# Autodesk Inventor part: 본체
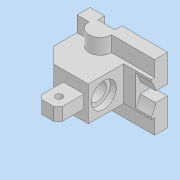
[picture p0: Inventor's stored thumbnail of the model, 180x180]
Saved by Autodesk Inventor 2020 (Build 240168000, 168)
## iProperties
Created: 2022-08
Part Number: 본체
Material: 일반
Document SubType Name: Modeling
Designer: MIRAE
Density: 1 g/cm^3
Appearance: 기본값
Author: MIRAE
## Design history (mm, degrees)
sketch "스케치1"
  geometry: L1 (-45, 38)-(45, 38); L2 (45, 38)-(45, -38); L3 (45, -38)-(-45, -38); L4 (-45, -38)-(-45, 38); L5 (-45, 38)-(45, -38); L6 (45, 38)-(-45, -38); 1 further point
  constraints: 12 end point, 2 midpoint, 2 parallel, 1 horizontal, 1 perpendicular
  dimensions: "d0" = 90 distance of L2.end L3.end; "d1" = 76 distance of L1.end L2.end
extrude "돌출1" new body sketch "스케치1" distance "d2" = 15; taper "d3" = 0 deg
sketch "스케치2"
  geometry: L1 (-45, 38)-(-45, -38) reference; L2 (-45, 20)-(13, 20); L3 (13, 20)-(13, -20); L4 (13, -20)-(-45, -20); L5 (-45, -20)-(-45, 20); L6 (-45, 0)-(64.688, 0); L7 (45, -38)-(45, 38) reference; 2 further points
  constraints: 10 end point, 2 horizontal, 2 midpoint, 2 parallel, 1 perpendicular, 1 point on line
  dimensions: "d4" = 40 distance between parallel lines of L4 L2; "d5" = 32 distance between parallel lines of L7 L3
extrude "돌출2" join sketch "스케치2" distance "d6" = 45; taper "d7" = 0 deg
chamfer "모따기1" distance "d8" = 18; stored, may be unused: second distance "d9" = 2, angle "d10" = 45 deg
sketch "스케치3"
  geometry: L1 (17, 8)-(37, 8); L2 (37, 8)-(37, -8.413); L3 (37, -8.413)-(17, -8.413); L4 (17, -8.413)-(17, 8); L5 (0, 0)-(90, 0) reference; L6 (27, 8)-(27, -18.381); L7 (0, 0)-(0, 15) reference; 1 further point
  constraints: 10 end point, 2 parallel, 1 horizontal, 1 midpoint, 1 perpendicular, 1 vertical
  dimensions: "d11" = 8 distance between parallel lines of L5 L1; "d12" = 27 distance between parallel lines of L7 L6; "d13" = 20 distance between parallel lines of L4 L2
extrude "돌출3" cut sketch "스케치3" extent not by distance; stored distance "d14" = 0; taper "d15" = 0 deg
sketch "스케치4"
  geometry: L1 (37, -7)-(17, -7) reference; L2 (27, -7)-(27, 0); L3 (0, 0)-(90, 0) reference; A1 r 13 centre (27, 0) between (40, 0) and (14, 0); 1 further point
  constraints: 3 point on line, 2 end point, 2 point on circle, 1 centre point, 1 coincident, 1 midpoint, 1 vertical
  dimensions: "d16" = 26 diameter of A1
extrude "돌출4" join sketch "스케치4" stored distance "d17" = 45; taper "d18" = 0 deg
sketch "스케치5"
  geometry: L1 (13, 20)-(13, -20) reference; L2 (45, -38)-(45, 38) reference; L3 (13, 20)-(45, 20); L4 (45, 20)-(45, -20); L5 (45, -20)-(13, -20); L6 (13, -20)-(13, 20); L7 (-27, -20)-(13, -20) reference; 2 further points
  constraints: 8 end point, 2 parallel, 2 point on line, 1 horizontal, 1 perpendicular
extrude "돌출5" join sketch "스케치5" distance "d19" = 4; taper "d20" = 0 deg
sketch "스케치6"
  geometry: L1 (16, 90)-(-8, 90); L2 (-8, 90)-(-8, 52.862); L3 (-8, 52.862)-(16, 52.862); L4 (16, 52.862)-(16, 90); L5 (-13, 60)-(27, 60) reference; L6 (-13, 19)-(-13, 60) reference; 1 further point
  constraints: 8 end point, 2 parallel, 1 horizontal, 1 perpendicular
  dimensions: "d21" = 5 distance between parallel lines of L6 L2; "d22" = 24 distance between parallel lines of L4 L2; "d23" = 30 distance between parallel lines of L5 L1
extrude "돌출6" join sketch "스케치6" stored distance "d24" = 15; taper "d25" = 0 deg
chamfer "모따기2" distance "d26" = 5; stored, may be unused: second distance "d27" = 2, angle "d28" = 45 deg
sketch "스케치7"
  geometry: L1 (60, -18)-(60, 58) reference; 4 further points
  constraints: 2 midpoint, 1 horizontal alignment
  dimensions: "d30" = 42 distance from line of L1 point (18, 20)
hole "구멍1" sketch "스케치7" at (18, 20) diameter "d31" = 20; stored, may be unused: countersink angle "d35" = 90 deg, drill point angle "d37" = 118 deg; dims "d32" = 3, "d33" = 29, "d34" = 7, "d36" = 8
sketch "스케치8"
  geometry: C1 r 10 at (-42, 38) reference; C2 r 29 at (-42, 38); 1 further point
  constraints: 1 centre point, 1 coincident
  dimensions: "d38" = 58 diameter of C2
extrude "돌출7" cut sketch "스케치8" distance "d39" = 18; taper "d40" = 0 deg
sketch "스케치9"
  geometry: L1 (8.301, 32)-(-17.655, 32); L2 (-17.655, 32)-(-17.655, 44); L3 (-17.655, 44)-(8.301, 44); L4 (8.301, 44)-(8.301, 32); L5 (0, 0)-(0, 76) reference; 3 further points
  constraints: 8 end point, 2 midpoint, 2 parallel, 1 horizontal, 1 horizontal alignment, 1 perpendicular
  dimensions: "d41" = 12 distance between parallel lines of L1 L3
extrude "돌출8" cut sketch "스케치9" distance "d42" = 18; taper "d43" = 0 deg
sketch "스케치10"
  geometry: L1 (-6, 56.5)-(-6, 27.5) reference; L2 (-6, 42)-(51.052, 42); L3 (-8, 85)-(-8, 60) reference; C1 r 4 at (4, 77); 1 further point
  constraints: 2 end point, 1 centre point, 1 horizontal, 1 midpoint
  dimensions: "d44" = 12 distance from line of L3 C1.centre; "d45" = 8 diameter of C1; "d46" = 35 distance from line of L2 C1.centre
extrude "돌출9" cut sketch "스케치10" extent not by distance; stored distance "d47" = 7.5; taper "d48" = 0 deg
node "솔리드1"
feature "A9D066F2-1C7D-4E18-AEED-F7BC21143FA4" dims "d31" = 20, "d32" = 3, "d33" = 29, "d34" = 7, "d35" = 90 deg, "d36" = 8, "d37" = 118 deg
